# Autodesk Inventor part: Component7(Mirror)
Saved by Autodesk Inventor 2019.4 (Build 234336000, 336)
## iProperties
Created: 2020-06
Part Number: Component7(Mirror)
Material: Generic
Document SubType Name: Modeling
Designer: Administrator
Density: 1 g/cm^3
Appearance: Default
Title: Component7(Mirror)
Author: Administrator
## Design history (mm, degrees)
